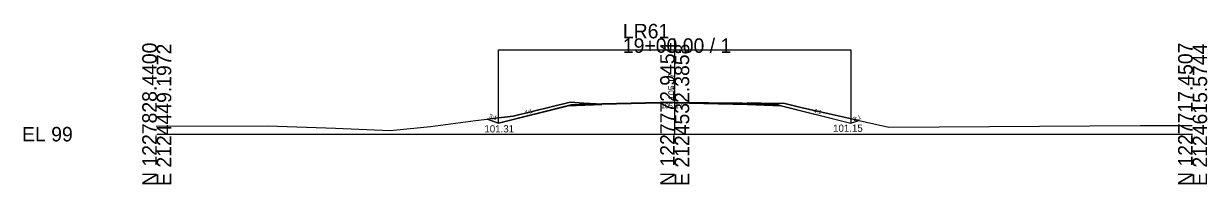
# Model space of a CAD drawing. Extents: x 2121193 to 2127979, y 1225108 to 1234639.
# Drawn here: x 2127750.9 to 2127979.4, y 1234107.5 to 1234138.6 of the extents above; entities that cross this region are included whole.
import ezdxf

# ---------------------------------------------------------------- set-up
doc = ezdxf.new("R2010")
doc.units = 0
for name, color, linetype in [('XS_CELL', 7, 'Continuous'), ('XS_M_DITCH', 7, 'Continuous'), ('XS_M_SHAPES_EARTHWORK', 7, 'Continuous'), ('XS_P_FINISHED_GRADE', 7, 'Continuous'), ('XS_P_FINISHED_GRADE_ELEV_TX', 7, 'Continuous'), ('XS_P_SUBGRADE_GRANULAR', 7, 'Continuous'), ('XS_P_SUBGRADE_PAVEMENT', 7, 'Continuous'), ('XS_P_TX_DCH', 7, 'Continuous'), ('XS_P_TX_FS_BS', 7, 'Continuous'), ('XS_X_GROUND', 7, 'Continuous'), ('XS_X_GROUND_TX', 7, 'Continuous')]:
    doc.layers.add(name, color=color, linetype=linetype)

msp = doc.modelspace()

# ---------------------------------------------------------------- linework, layer by layer
at = {"layer": 'XS_CELL'}
for p, q in [((2127876.61, 1234117.21), (2127876.61, 1234135.72)), ((2127776.61, 1234117.21), (2127876.61, 1234117.21)), ((2127876.61, 1234117.21), (2127976.61, 1234117.21))]:
    msp.add_line(p, q, dxfattribs=at)
at = {"layer": 'XS_M_DITCH'}
for p, q in [((2127842.61, 1234119.36), (2127842.61, 1234133.47)), ((2127842.61, 1234133.47), (2127910.61, 1234133.47)), ((2127910.61, 1234133.47), (2127910.61, 1234119.36))]:
    msp.add_line(p, q, dxfattribs=at)
at = {"layer": 'XS_M_SHAPES_EARTHWORK'}
for p, q in [((2127842.61, 1234119.36), (2127856.02, 1234122.71)), ((2127856.44, 1234123.38), (2127845.45, 1234120.67)), ((2127856.02, 1234122.71), (2127862.54, 1234122.97)), ((2127856.61, 1234122.86), (2127856.02, 1234122.71)), ((2127856.02, 1234122.71), (2127856.61, 1234122.86)), ((2127859.08, 1234123.21), (2127856.44, 1234123.38)), ((2127861.42, 1234123.05), (2127856.61, 1234122.86)), ((2127856.61, 1234122.86), (2127861.42, 1234123.05)), ((2127861.42, 1234123.05), (2127859.08, 1234123.21)), ((2127862.11, 1234123.01), (2127861.42, 1234123.05)), ((2127862.56, 1234123.02), (2127862.11, 1234123.01)), ((2127862.54, 1234122.97), (2127862.56, 1234123.02)), ((2127896.1, 1234123.15), (2127890.61, 1234123.26)), ((2127890.61, 1234123.26), (2127890.61, 1234123.1)), ((2127896.61, 1234122.86), (2127890.61, 1234123.1)), ((2127890.61, 1234123.1), (2127890.68, 1234122.97)), ((2127890.61, 1234123.1), (2127896.61, 1234122.86)), ((2127890.68, 1234122.97), (2127897.2, 1234122.71)), ((2127897.63, 1234123.2), (2127896.1, 1234123.15)), ((2127897.2, 1234122.71), (2127896.61, 1234122.86)), ((2127900.73, 1234122.45), (2127897.63, 1234123.2)), ((2127912.17, 1234119.88), (2127900.73, 1234122.45)), ((2127845.45, 1234120.67), (2127840.4, 1234120.1)), ((2127840.4, 1234120.1), (2127842.61, 1234119.36)), ((2127910.61, 1234119.36), (2127912.17, 1234119.88))]:
    msp.add_line(p, q, dxfattribs=at)
msp.add_lwpolyline([(2127896.61, 1234122.86), (2127897.2, 1234122.71), (2127910.61, 1234119.36)], dxfattribs=at)
at = {"layer": 'XS_P_FINISHED_GRADE'}
for p, q in [((2127856.61, 1234122.86), (2127842.61, 1234119.36)), ((2127862.61, 1234123.1), (2127856.61, 1234122.86)), ((2127876.61, 1234123.38), (2127862.61, 1234123.1)), ((2127876.61, 1234123.38), (2127890.61, 1234123.1)), ((2127890.61, 1234123.1), (2127896.61, 1234122.86)), ((2127896.61, 1234122.86), (2127910.61, 1234119.36)), ((2127842.61, 1234119.36), (2127840.4, 1234120.1)), ((2127910.61, 1234119.36), (2127912.17, 1234119.88))]:
    msp.add_line(p, q, dxfattribs=at)
at = {"layer": 'XS_P_SUBGRADE_GRANULAR'}
for p, q in [((2127862.54, 1234122.97), (2127856.02, 1234122.71)), ((2127890.68, 1234122.97), (2127897.2, 1234122.71))]:
    msp.add_line(p, q, dxfattribs=at)
at = {"layer": 'XS_P_SUBGRADE_PAVEMENT'}
for p, q in [((2127876.61, 1234123.25), (2127862.54, 1234122.97)), ((2127862.61, 1234123.1), (2127862.54, 1234122.97)), ((2127876.61, 1234123.25), (2127890.68, 1234122.97)), ((2127890.61, 1234123.1), (2127890.68, 1234122.97))]:
    msp.add_line(p, q, dxfattribs=at)
at = {"layer": 'XS_X_GROUND'}
for p, q in [((2127845.45, 1234120.67), (2127856.44, 1234123.38)), ((2127856.44, 1234123.38), (2127859.08, 1234123.21)), ((2127859.08, 1234123.21), (2127862.11, 1234123.01)), ((2127862.11, 1234123.01), (2127865.93, 1234123.11)), ((2127865.93, 1234123.11), (2127876.61, 1234123.38)), ((2127876.61, 1234123.38), (2127889.7, 1234123.28)), ((2127889.7, 1234123.28), (2127896.1, 1234123.15)), ((2127896.1, 1234123.15), (2127897.63, 1234123.2)), ((2127897.63, 1234123.2), (2127900.73, 1234122.45)), ((2127900.73, 1234122.45), (2127917.97, 1234118.58)), ((2127829.48, 1234118.68), (2127838.15, 1234119.84)), ((2127838.15, 1234119.84), (2127845.45, 1234120.67)), ((2127776.51, 1234118.78), (2127798.06, 1234118.84)), ((2127798.06, 1234118.84), (2127811.09, 1234118.39)), ((2127811.09, 1234118.39), (2127821.68, 1234117.94)), ((2127821.68, 1234117.94), (2127829.48, 1234118.68)), ((2127917.97, 1234118.58), (2127966.45, 1234118.89)), ((2127966.45, 1234118.89), (2127976.51, 1234118.9))]:
    msp.add_line(p, q, dxfattribs=at)

# ---------------------------------------------------------------- texts
at = {"layer": 'XS_CELL'}
for s, p in [('LR61', (2127866.61, 1234135.72)), ('19+00.00 / 1', (2127866.61, 1234132.92)), ('EL 99', (2127750.61, 1234115.81))]:
    msp.add_text(s, height=2.8, dxfattribs=at).set_placement(p)
for s, p in [('N 1227828.4400', (2127776.61, 1234107.21)), ('E 2124449.1972', (2127779.41, 1234107.21)), ('N 1227772.9454', (2127876.61, 1234107.21)), ('E 2124532.3858', (2127879.41, 1234107.21)), ('N 1227717.4507', (2127976.61, 1234107.21)), ('E 2124615.5744', (2127979.41, 1234107.21))]:
    msp.add_text(s, height=2.8, rotation=90, dxfattribs=at).set_placement(p)
at = {"layer": 'XS_P_FINISHED_GRADE_ELEV_TX'}
msp.add_text(' 105.17', height=1.25, rotation=90, dxfattribs=at).set_placement((2127876.61, 1234123.37))
at = {"layer": 'XS_P_TX_DCH'}
for s, p in [('101.31', (2127839.87, 1234117.54)), ('101.15', (2127907.19, 1234117.66))]:
    msp.add_text(s, height=1.4, dxfattribs=at).set_placement(p)
at = {"layer": 'XS_P_TX_FS_BS'}
for s, rotation, p in [('4:1', 14.0362, (2127847.74, 1234120.96)), ('4:1', 345.9638, (2127903.38, 1234121.42)), ('3:1', 341.5651, (2127840.69, 1234120.4)), ('3:1', 18.4349, (2127911.21, 1234119.7))]:
    msp.add_text(s, height=0.8, rotation=rotation, dxfattribs=at).set_placement(p)
at = {"layer": 'XS_X_GROUND_TX'}
msp.add_text('105.17', height=1, dxfattribs=at).set_placement((2127873.95, 1234122.21))

doc.saveas('drawing.dxf')
